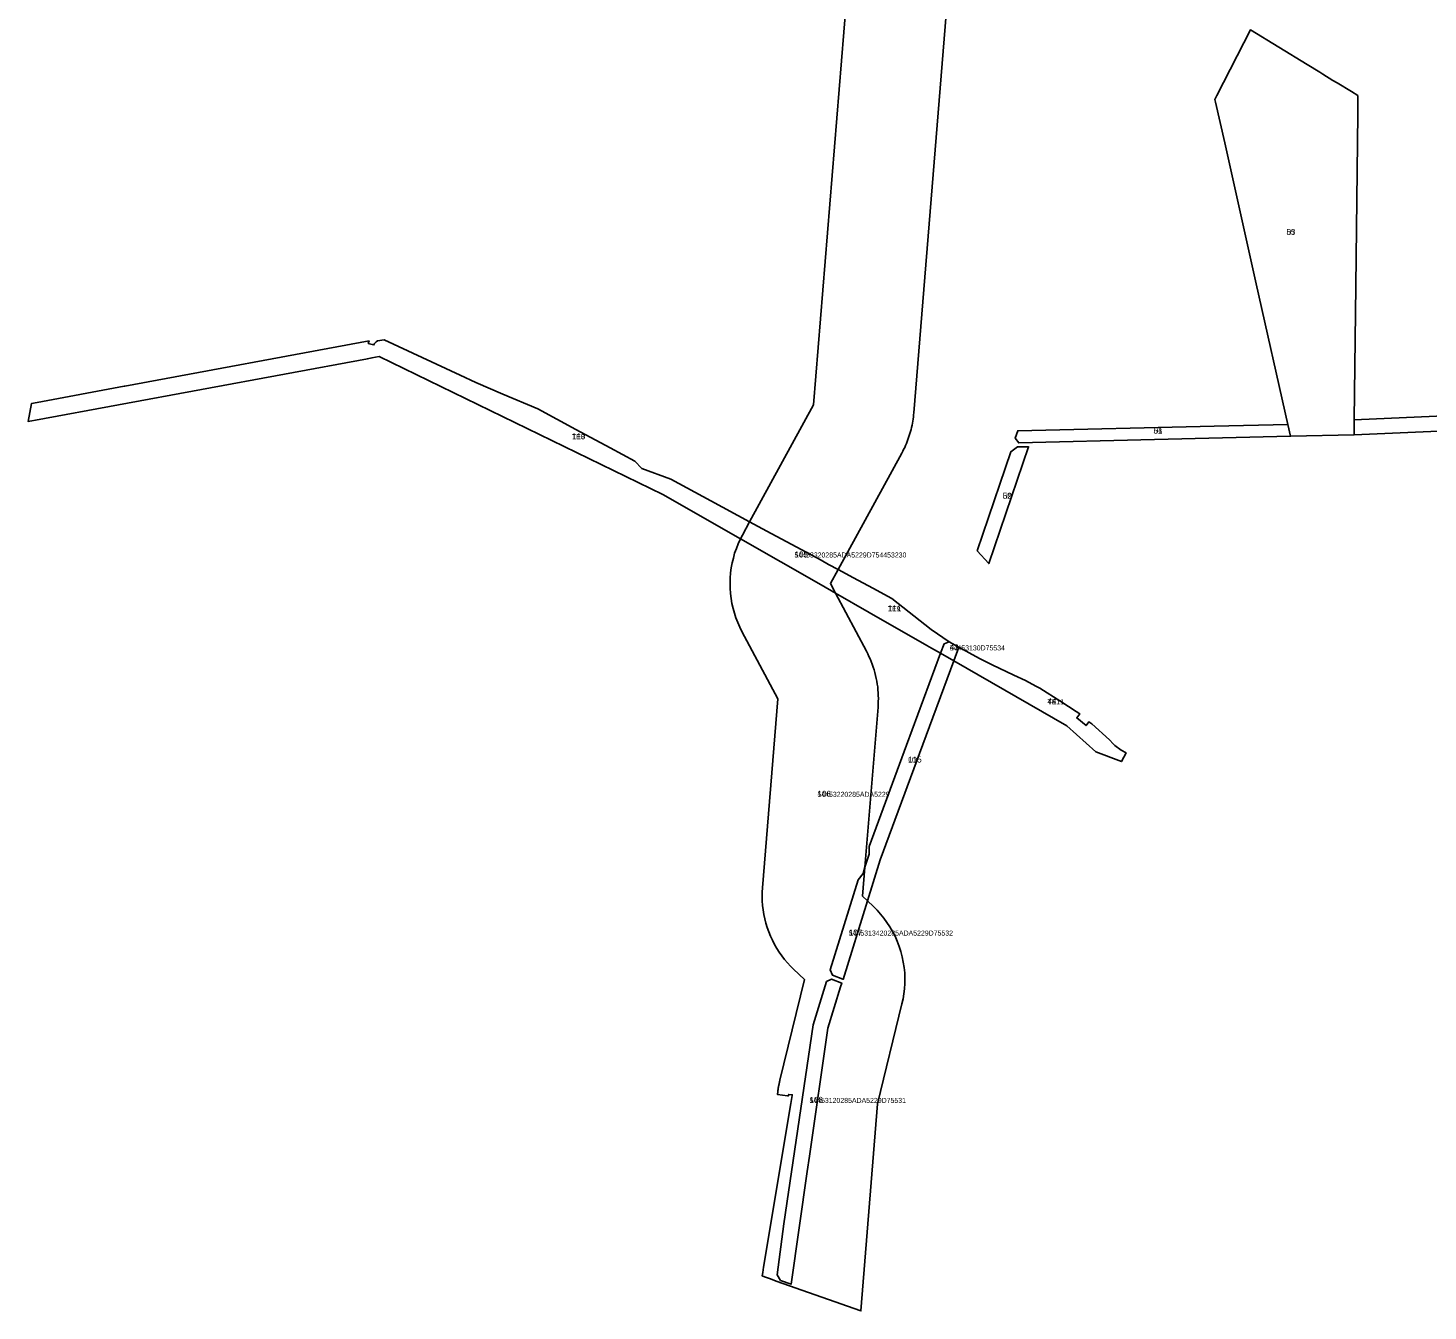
# Model space of a CAD drawing. Extents: x -545623 to -541713, y -1153152 to -1149975.
# Drawn here: x -545623 to -544231, y -1153152 to -1151876 of the extents above; entities that cross this region are included whole.
import ezdxf

# ---------------------------------------------------------------- set-up
doc = ezdxf.new("R2010")
doc.units = 0
for name, color, linetype in [('96120023', 7, 'Continuous'), ('96140023', 7, 'Continuous'), ('ID_VPO', 7, 'Continuous'), ('ID_VPS', 7, 'Continuous')]:
    doc.layers.add(name, color=color, linetype=linetype)

msp = doc.modelspace()

# ---------------------------------------------------------------- linework, layer by layer
at = {"layer": '96120023'}
msp.add_lwpolyline([(-544642.4, -1151028.2), (-544742.3, -1152258.6), (-544742.5, -1152260.7), (-544742.7, -1152262.8), (-544743, -1152264.9), (-544743.3, -1152267), (-544743.7, -1152269), (-544744.1, -1152271.1), (-544744.6, -1152273.2), (-544745.1, -1152275.2), (-544745.6, -1152277.3), (-544746.2, -1152279.3), (-544746.8, -1152281.4), (-544747.5, -1152283.4), (-544748.2, -1152285.4), (-544748.9, -1152287.3), (-544749.7, -1152289.3), (-544750.6, -1152291.2), (-544751.4, -1152293.2), (-544752.4, -1152295.1), (-544753.3, -1152296.9), (-544754.3, -1152298.8), (-544817.6, -1152414.6), (-544827.2, -1152409.4), (-544834.6, -1152405.4), (-544888.4, -1152376.4), (-544905.6, -1152367.1), (-544905.6, -1152367.1), (-544842, -1152250.7), (-544744.7, -1151053)], dxfattribs=at)
for points in [[(-544912.8, -1152380.3), (-544914.7, -1152384), (-544991.8, -1152339.8), (-545274, -1152202.7), (-545281.4, -1152204.1), (-545285.8, -1152204.9), (-545616, -1152265.9), (-545623.4, -1152267.2), (-545619.8, -1152249.3), (-545614.4, -1152248.3), (-545527.6, -1152232.2), (-545527.5, -1152232.3), (-545527, -1152232.1), (-545284.1, -1152187.3), (-545285, -1152189.7), (-545281, -1152190.7), (-545279.4, -1152191.2), (-545278.6, -1152189.9), (-545277, -1152188.2), (-545275.7, -1152187.3), (-545269, -1152186.2), (-545193.4, -1152221.4), (-545178, -1152228.5), (-545151.1, -1152240.1), (-545116.4, -1152254.8), (-545078.5, -1152275.2), (-545044.4, -1152293.6), (-545019.7, -1152306.9), (-545012.7, -1152314), (-544983.9, -1152324.8), (-544944.1, -1152346.2), (-544905.6, -1152367.1)], [(-544834.4, -1152429.9), (-544914.7, -1152384), (-544912.8, -1152380.3), (-544905.6, -1152367.1), (-544888.4, -1152376.4), (-544834.6, -1152405.4), (-544827.2, -1152409.4), (-544817.6, -1152414.6), (-544825.2, -1152428.6), (-544820.2, -1152438.1)], [(-544892.6, -1153113.7), (-544891.7, -1153108.2), (-544864.7, -1152945.7), (-544863.3, -1152937.6), (-544863.2, -1152936.8), (-544866.7, -1152936.5), (-544866.8, -1152936.9), (-544867, -1152938), (-544867.9, -1152937.9), (-544877.9, -1152936.6), (-544877.9, -1152936.5), (-544877.8, -1152935.7), (-544877.7, -1152934.9), (-544877.6, -1152934.1), (-544877.5, -1152933.3), (-544877.4, -1152932.5), (-544877.3, -1152931.7), (-544877.2, -1152930.9), (-544877.1, -1152930.1), (-544876.9, -1152929.3), (-544876.8, -1152928.5), (-544876.7, -1152927.7), (-544876.5, -1152927), (-544876.4, -1152926.2), (-544876.2, -1152925.4), (-544876, -1152924.6), (-544875.8, -1152923.8), (-544875.7, -1152923), (-544875.5, -1152922.3), (-544851.1, -1152822.4), (-544862, -1152812), (-544865.1, -1152808.9), (-544868.1, -1152805.7), (-544870.9, -1152802.3), (-544873.6, -1152798.8), (-544876.2, -1152795.1), (-544878.6, -1152791.3), (-544880.9, -1152787.3), (-544883, -1152783.3), (-544884.9, -1152779.2), (-544886.6, -1152775), (-544888.1, -1152770.7), (-544889.4, -1152766.3), (-544890.6, -1152761.9), (-544891.5, -1152757.5), (-544892.2, -1152753), (-544892.7, -1152748.6), (-544893, -1152744.1), (-544893.2, -1152739.7), (-544893.1, -1152735.3), (-544892.8, -1152731), (-544877.5, -1152543.1), (-544913.3, -1152476.1), (-544915.4, -1152471.8), (-544917.4, -1152467.3), (-544919.2, -1152462.7), (-544920.7, -1152458), (-544922.1, -1152453.2), (-544923.2, -1152448.3), (-544924.1, -1152443.3), (-544924.7, -1152438.3), (-544925, -1152433.2), (-544925.1, -1152428.1), (-544925, -1152423), (-544924.6, -1152418), (-544923.9, -1152412.9), (-544923, -1152408), (-544921.8, -1152403.1), (-544920.5, -1152398.3), (-544918.8, -1152393.6), (-544917, -1152389), (-544915, -1152384.6), (-544914.7, -1152384), (-544834.4, -1152429.9), (-544820.2, -1152438.1), (-544789.4, -1152495.8), (-544788.1, -1152498.3), (-544786.9, -1152500.9), (-544785.7, -1152503.5), (-544784.6, -1152506.1), (-544783.6, -1152508.8), (-544782.6, -1152511.6), (-544781.8, -1152514.3), (-544781, -1152517.1), (-544780.3, -1152519.9), (-544779.6, -1152522.8), (-544779.1, -1152525.6), (-544778.6, -1152528.5), (-544778.2, -1152531.3), (-544778, -1152534.2), (-544777.7, -1152537.1), (-544777.6, -1152540), (-544777.5, -1152542.8), (-544777.6, -1152545.7), (-544777.7, -1152548.6), (-544777.9, -1152551.4), (-544790.9, -1152710.7), (-544792.8, -1152716.8), (-544797.5, -1152723.1), (-544825.6, -1152812.8), (-544823.1, -1152818.1), (-544812.9, -1152822), (-544812.7, -1152822.1), (-544788.3, -1152744.1), (-544782.3, -1152749.8), (-544778.8, -1152753.4), (-544775.3, -1152757.3), (-544772.1, -1152761.3), (-544769, -1152765.5), (-544766.1, -1152770), (-544763.4, -1152774.6), (-544761, -1152779.3), (-544758.8, -1152784.3), (-544756.9, -1152789.3), (-544755.2, -1152794.4), (-544753.9, -1152799.7), (-544752.8, -1152804.9), (-544752, -1152810.3), (-544751.4, -1152815.6), (-544751.2, -1152820.9), (-544751.3, -1152826.2), (-544751.6, -1152831.4), (-544752.2, -1152836.6), (-544753, -1152841.6), (-544754.1, -1152846.6), (-544778.4, -1152946), (-544794.9, -1153151.9), (-544879.1, -1153122.1), (-544884.7, -1153120), (-544889.9, -1153118.2), (-544892.5, -1153117.2), (-544893.2, -1153116.9)], [(-544820.2, -1152438.1), (-544825.2, -1152428.6), (-544817.6, -1152414.6), (-544802.2, -1152422.9), (-544783.1, -1152433.2), (-544764.1, -1152443.5), (-544725.2, -1152474.3), (-544707.3, -1152486.6), (-544712.2, -1152488.4), (-544715.7, -1152497.9), (-544724.7, -1152492.8), (-544729.5, -1152490), (-544786.7, -1152457.3)], [(-544702.5, -1152505.5), (-544715.7, -1152497.9), (-544712.2, -1152488.4), (-544707.3, -1152486.6), (-544697.5, -1152491.8)], [(-544561.1, -1152595.8), (-544590, -1152569.9), (-544702.5, -1152505.5), (-544697.5, -1152491.8), (-544676.9, -1152502.9), (-544664.4, -1152509.4), (-544642.9, -1152519.5), (-544631.3, -1152525), (-544621.1, -1152530.5), (-544617, -1152532.7), (-544596.2, -1152545.8), (-544580.8, -1152555.6), (-544577.1, -1152558.1), (-544580.3, -1152562.1), (-544571, -1152569.7), (-544568.1, -1152565.9), (-544565.3, -1152568.1), (-544547.6, -1152583.9), (-544543.9, -1152587.8), (-544542.2, -1152589.6), (-544536.2, -1152594.2), (-544531.2, -1152596.9), (-544535.8, -1152605.5)], [(-544792.8, -1152716.8), (-544790.9, -1152710.7), (-544793.2, -1152739.5), (-544788.3, -1152744.1), (-544812.7, -1152822.1), (-544812.9, -1152822), (-544823.1, -1152818.1), (-544825.6, -1152812.8), (-544797.5, -1152723.1)], [(-544864.4, -1153125.3), (-544848.3, -1153013.3), (-544846.1, -1152998), (-544827.9, -1152870.8), (-544815.1, -1152829.7), (-544814, -1152825.9), (-544824.3, -1152821.9), (-544829.1, -1152824.3), (-544834.5, -1152841.6), (-544842.5, -1152867.5), (-544871.5, -1153065.1), (-544878.2, -1153115.9), (-544874.8, -1153121.5)], [(-544848.3, -1153013.3), (-544864.4, -1153125.3), (-544874.8, -1153121.5), (-544878.2, -1153115.9), (-544871.5, -1153065.1), (-544842.5, -1152867.5), (-544834.5, -1152841.6), (-544829.1, -1152824.3), (-544824.3, -1152821.9), (-544814, -1152825.9), (-544815.1, -1152829.7), (-544827.9, -1152870.8), (-544846.1, -1152998)]]:
    msp.add_lwpolyline(points, close=True, dxfattribs=at)
at = {"layer": '96140023'}
for points in [[(-544335.3, -1151922.1), (-544325.4, -1151928.1), (-544321.3, -1151930.6), (-544307, -1151939.3), (-544300.6, -1151943.2), (-544300.8, -1151957.5), (-544300.8, -1151961.3), (-544302.8, -1152132.7), (-544304.3, -1152265.6), (-544304.4, -1152280.6), (-544367.6, -1152282.1), (-544370.3, -1152270.2), (-544401.7, -1152130.3), (-544421.1, -1152043.9), (-544421.1, -1152043.9), (-544433.1, -1151990.3), (-544442.2, -1151949.7), (-544442.8, -1151947.2), (-544440.8, -1151943.2), (-544407.5, -1151878), (-544351.1, -1151912.4), (-544338.6, -1151920.1)], [(-544167.1, -1152274.5), (-544167.1, -1152274.5), (-544304.4, -1152280.6), (-544304.3, -1152265.6), (-544162.8, -1152259.3), (-544144.4, -1152258.5), (-544098.5, -1152256.4), (-544051.4, -1152254.4), (-544020.4, -1152253), (-544024.4, -1152264.5), (-544029.7, -1152268.4)], [(-544502.8, -1152285.4), (-544638, -1152288.6), (-544641.4, -1152284), (-544639, -1152276.6), (-544443.7, -1152271.9), (-544370.3, -1152270.2), (-544367.6, -1152282.1)], [(-544679.3, -1152395.9), (-544656.6, -1152329.7), (-544645.9, -1152297.5), (-544639.3, -1152292.6), (-544628.2, -1152292.4), (-544667.8, -1152408.6)], [(-544702.5, -1152505.5), (-544715.7, -1152497.9), (-544712.2, -1152488.4), (-544707.3, -1152486.6), (-544697.5, -1152491.8)], [(-544790.9, -1152710.7), (-544786.6, -1152697.7), (-544786.7, -1152690.1), (-544749.5, -1152589.2), (-544715.7, -1152497.9), (-544702.5, -1152505.5), (-544736.6, -1152597.6), (-544775.7, -1152703.4), (-544788.3, -1152744.1), (-544793.2, -1152739.5)], [(-544793.2, -1152739.5), (-544788.3, -1152744.1), (-544812.7, -1152822.1), (-544812.9, -1152822), (-544823.1, -1152818.1), (-544825.6, -1152812.8), (-544797.5, -1152723.1), (-544792.8, -1152716.8), (-544790.9, -1152710.7)], [(-544848.3, -1153013.3), (-544864.4, -1153125.3), (-544874.8, -1153121.5), (-544878.2, -1153115.9), (-544871.5, -1153065.1), (-544842.5, -1152867.5), (-544834.5, -1152841.6), (-544829.1, -1152824.3), (-544824.3, -1152821.9), (-544814, -1152825.9), (-544815.1, -1152829.7), (-544827.9, -1152870.8), (-544846.1, -1152998)]]:
    msp.add_lwpolyline(points, close=True, dxfattribs=at)

# ---------------------------------------------------------------- texts
at = {"layer": '96120023'}
for s, rotation, p in [('TE8', 360, (-545082.3, -1152285.1)), ('54453320285ADA5229D754453230', 0, (-544861, -1152402.6)), ('TE9', 0, (-544768.2, -1152456.2)), ('54453130D75534', 360, (-544706.6, -1152495)), ('TE11', 360, (-544609.4, -1152548.6)), ('54453220285ADA5229', 0, (-544838.2, -1152640.6)), ('5445313420285ADA5229D75532', 0, (-544807, -1152778.6)), ('54453120285ADA5229D75531', 360, (-544846.1, -1152945))]:
    msp.add_text(s, height=5, rotation=rotation, dxfattribs=at).set_placement(p)
at = {"layer": '96140023'}
for s, rotation, p in [('U7', 360, (-544371.7, -1152081.8)), ('U6', 0, (-544504, -1152279.4)), ('54453130D75534', 360, (-544706.6, -1152495)), ('U3', 0, (-544747.9, -1152606.5)), ('5445313420285ADA5229D75532', 0, (-544807, -1152778.6)), ('54453120285ADA5229D75531', 360, (-544846.1, -1152945))]:
    msp.add_text(s, height=5, rotation=rotation, dxfattribs=at).set_placement(p)
msp.add_text('U5', height=5, dxfattribs=at).set_placement((-544653.8, -1152344.2))
at = {"layer": 'ID_VPO'}
for s, rotation, p in [('55', 360, (-544371.7, -1152081.8)), ('51', 360, (-544504, -1152279.4)), ('52', 0, (-544653.8, -1152344.2)), ('43', 360, (-544706.6, -1152495)), ('115', 0, (-544747.9, -1152606.5)), ('107', 0, (-544807, -1152778.6)), ('108', 360, (-544846.1, -1152945))]:
    msp.add_text(s, height=6, rotation=rotation, dxfattribs=at).set_placement(p)
at = {"layer": 'ID_VPS'}
for s, rotation, p in [('110', 0, (-545082.3, -1152285.1)), ('105', 360, (-544861, -1152402.6)), ('111', 0, (-544768.2, -1152456.2)), ('43', 360, (-544706.6, -1152495)), ('44', 360, (-544609.4, -1152548.6)), ('106', 0, (-544838.2, -1152640.6)), ('107', 0, (-544807, -1152778.6)), ('108', 360, (-544846.1, -1152945))]:
    msp.add_text(s, height=6, rotation=rotation, dxfattribs=at).set_placement(p)

doc.saveas('drawing.dxf')
